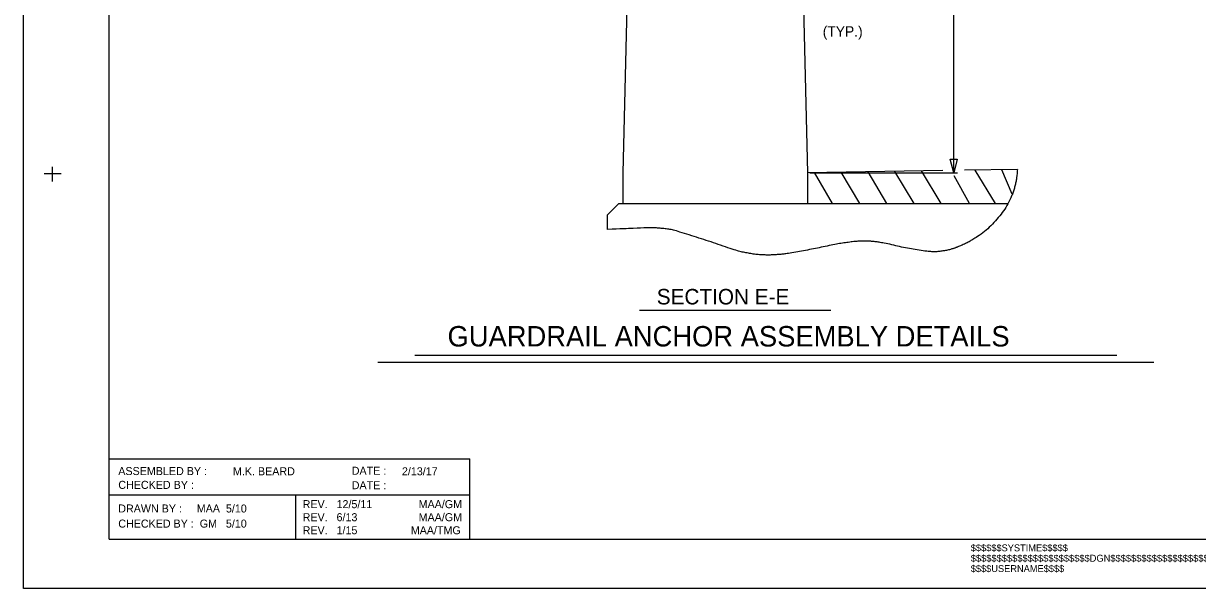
# Model space of a CAD drawing. Extents: x -3.7 to 10.9, y 0 to 8.5.
# Drawn here: x 0 to 4.767, y 0 to 2.294 of the extents above; entities that cross this region are included whole.
import ezdxf

# ---------------------------------------------------------------- set-up
doc = ezdxf.new("R2010")
doc.units = 0
for name, color, linetype in [('Arrowhead Terminators', 7, 'Continuous'), ('Box Beam', 7, 'Continuous'), ('Cored Slab Unit CELL', 7, 'Continuous'), ('Dimension Lines', 7, 'Continuous'), ('Mis Object Lines', 7, 'Continuous'), ('Plan Sheet', 7, 'Continuous'), ('Plan Sheet CELL', 7, 'Continuous'), ('Plot Label', 7, 'Continuous'), ('Plot Shape', 7, 'Continuous'), ('Subtitle Text', 7, 'Continuous'), ('Sup Concrete Barrier Rail CELL', 7, 'Continuous'), ('Text', 7, 'Continuous'), ('Title Text', 7, 'Continuous'), ('User Information Notes', 7, 'Continuous')]:
    doc.layers.add(name, color=color, linetype=linetype)

msp = doc.modelspace()

# ---------------------------------------------------------------- linework, layer by layer
at = {"layer": 'Arrowhead Terminators'}
msp.add_lwpolyline([(3.791, 1.7436), (3.777, 1.6876), (3.763, 1.7436)], close=True, dxfattribs=at)
at = {"layer": 'Box Beam'}
for p, q in [((2.4173, 1.5626), (2.3704, 1.5158)), ((2.3704, 1.5158), (2.3704, 1.4578))]:
    msp.add_line(p, q, dxfattribs=at)
at = {"layer": 'Cored Slab Unit CELL'}
for p, q in [((2.4173, 1.5626), (2.4329, 1.5626)), ((2.4329, 1.5626), (3.1829, 1.5626)), ((3.1829, 1.5626), (3.9965, 1.5626))]:
    msp.add_line(p, q, dxfattribs=at)
for points in [[(2.4954, 4.2658), (2.4329, 1.6877), (2.4329, 1.5626)], [(3.1204, 4.2658), (3.1829, 1.6876), (3.1829, 1.5626)]]:
    msp.add_lwpolyline(points, dxfattribs=at)
at = {"layer": 'Dimension Lines'}
for p, q in [((3.777, 1.6876), (3.777, 3.1251)), ((3.1925, 1.6876), (3.7927, 1.6876))]:
    msp.add_line(p, q, dxfattribs=at)
at = {"layer": 'Mis Object Lines'}
for p, q in [((3.7325, 1.6964), (3.1829, 1.6877)), ((3.2852, 1.5626), (3.2115, 1.6882)), ((3.3954, 1.5626), (3.3203, 1.6899)), ((3.5056, 1.5626), (3.4291, 1.6916)), ((3.6158, 1.5626), (3.5379, 1.6933)), ((3.726, 1.5626), (3.6467, 1.695)), ((3.8405, 1.5626), (3.7781, 1.6748)), ((4.0353, 1.7011), (3.8203, 1.6977)), ((3.9464, 1.5626), (3.8642, 1.6984)), ((4.0145, 1.6005), (3.9727, 1.7001))]:
    msp.add_line(p, q, dxfattribs=at)
at = {"layer": 'Plan Sheet'}
for p, q in [((0.3479, 0.2), (0.3479, 7.13)), ((0.0842, 1.6851), (0.1535, 1.6851)), ((0.118, 1.6523), (0.118, 1.7121)), ((0.3479, 0.5258), (1.8116, 0.5258)), ((1.8116, 0.2), (1.8116, 0.5258)), ((1.8116, 0.5258), (1.8116, 0.5258)), ((1.8116, 0.379), (0.3479, 0.379)), ((1.1054, 0.2), (1.1054, 0.379)), ((0.3479, 0.2), (10.908, 0.2)), ((0.3479, 0.2), (1.8116, 0.2)), ((0, 0), (0, 0))]:
    msp.add_line(p, q, dxfattribs=at)
at = {"layer": 'Plan Sheet CELL'}
msp.add_line((0, 0), (0, 0), dxfattribs=at)
msp.add_line((0, 0), (0, 0), dxfattribs=at)
at = {"layer": 'Plot Shape'}
msp.add_lwpolyline([(0, 7.26), (10.9109, 7.26), (10.9109, 0), (0, 0)], close=True, dxfattribs=at)
at = {"layer": 'Subtitle Text'}
msp.add_line((2.5012, 1.1298), (3.2785, 1.1298), dxfattribs=at)
at = {"layer": 'Sup Concrete Barrier Rail CELL'}
msp.add_open_spline([(4.0353, 1.7011), (4.0347, 1.692), (4.0338, 1.683), (4.0329, 1.6739), (4.0313, 1.6574), (4.0274, 1.6414), (4.0231, 1.6253), (4.0188, 1.6089), (4.0123, 1.5935), (4.0046, 1.5782), (3.9888, 1.5468), (3.9699, 1.5187), (3.946, 1.4926), (3.9216, 1.4659), (3.8955, 1.4431), (3.8655, 1.4238), (3.8506, 1.4143), (3.8356, 1.4054), (3.8197, 1.3979), (3.8118, 1.3943), (3.8039, 1.3907), (3.7958, 1.3875), (3.7918, 1.3859), (3.7878, 1.3844), (3.7837, 1.383), (3.7797, 1.3815), (3.7756, 1.3802), (3.7715, 1.3789), (3.756, 1.3741), (3.7401, 1.3712), (3.7241, 1.3692), (3.7083, 1.3672), (3.6922, 1.3665), (3.6765, 1.3683), (3.6446, 1.3719), (3.6128, 1.3769), (3.5812, 1.3831), (3.5492, 1.3893), (3.5179, 1.3977), (3.4859, 1.4035), (3.4702, 1.4063), (3.4544, 1.4083), (3.4384, 1.4097), (3.4305, 1.4104), (3.4226, 1.4107), (3.4147, 1.4107), (3.4068, 1.4107), (3.399, 1.4105), (3.3911, 1.4099), (3.3831, 1.4094), (3.3751, 1.4087), (3.3671, 1.4077), (3.343, 1.4046), (3.319, 1.4012), (3.2952, 1.3967), (3.2631, 1.3906), (3.2313, 1.3834), (3.1993, 1.3772), (3.1674, 1.371), (3.1355, 1.3652), (3.1034, 1.3601), (3.0876, 1.3575), (3.0716, 1.3563), (3.0556, 1.3551), (3.0397, 1.354), (3.0237, 1.3537), (3.0078, 1.3541), (2.9879, 1.3547), (2.968, 1.3568), (2.9482, 1.3603), (2.9282, 1.3638), (2.9085, 1.3678), (2.8892, 1.374), (2.8499, 1.3866), (2.8111, 1.4004), (2.7719, 1.4132), (2.7328, 1.4259), (2.6937, 1.4384), (2.6542, 1.4504), (2.6348, 1.4562), (2.6148, 1.4595), (2.5947, 1.4616), (2.5746, 1.4636), (2.5545, 1.4651), (2.5344, 1.4643), (2.4797, 1.4621), (2.4251, 1.46), (2.3704, 1.4578)], degree=3, dxfattribs=at)
at = {"layer": 'Title Text'}
for p, q in [((4.5892, 0.9175), (1.4389, 0.9175)), ((4.4391, 0.9455), (1.589, 0.9455))]:
    msp.add_line(p, q, dxfattribs=at)
at = {"layer": 'User Information Notes'}
for p, q in [((1.1335, 0.3587), (1.1335, 0.3587)), ((1.1335, 0.3057), (1.1335, 0.3057)), ((1.1335, 0.2527), (1.1335, 0.2527)), ((0, 0), (0, 0))]:
    msp.add_line(p, q, dxfattribs=at)

# ---------------------------------------------------------------- texts
at = {"layer": 'Plan Sheet'}
for s, height, p in [('ASSEMBLED BY :', 0.032531, (0.3849, 0.4606)), ('DATE :', 0.03253, (1.3328, 0.4619)), ('CHECKED BY :', 0.032531, (0.3849, 0.4045)), ('DATE :', 0.03253, (1.3328, 0.4031)), ('DRAWN BY :     MAA  5/10', 0.0325, (0.3849, 0.3086)), ('REV.   12/5/11', 0.0325, (1.1335, 0.3262)), ('MAA/GM', 0.0325, (1.6044, 0.3262)), ('REV.   6/13', 0.0325, (1.1335, 0.2732)), ('MAA/GM', 0.0325, (1.6044, 0.2732)), ('CHECKED BY :  GM   5/10', 0.032494, (0.3849, 0.2473)), ('REV.   1/15', 0.0325, (1.1335, 0.2202)), ('MAA/TMG', 0.0325, (1.5726, 0.2202))]:
    msp.add_text(s, height=height, dxfattribs=at).set_placement(p)
at = {"layer": 'Plot Label'}
for s, height, p in [('$$$$$$SYSTIME$$$$$', 0.028062, (3.8461, 0.151)), ('$$$$USERNAME$$$$', 0.028062, (3.8461, 0.0668)), ('$$$$$$$$$$$$$$$$$$$$$$$DGN$$$$$$$$$$$$$$$$$$$$$$$', 0.028234, (3.8461, 0.1089))]:
    msp.add_text(s, height=height, dxfattribs=at).set_placement(p)
at = {"layer": 'Subtitle Text'}
msp.add_text('SECTION E-E', height=0.063, dxfattribs=at).set_placement((2.5712, 1.1532))
at = {"layer": 'Text'}
msp.add_text('(TYP.)', height=0.04198, rotation=360, dxfattribs=at).set_placement((3.2451, 2.2405))
for s, p in [('M.K. BEARD', (0.8505, 0.4596)), ('2/13/17', (1.5365, 0.4596))]:
    msp.add_text(s, height=0.03253, dxfattribs=at).set_placement(p)
at = {"layer": 'Title Text'}
msp.add_text('GUARDRAIL ANCHOR ASSEMBLY DETAILS', height=0.083, dxfattribs=at).set_placement((1.7218, 0.9825))

doc.saveas('drawing.dxf')
